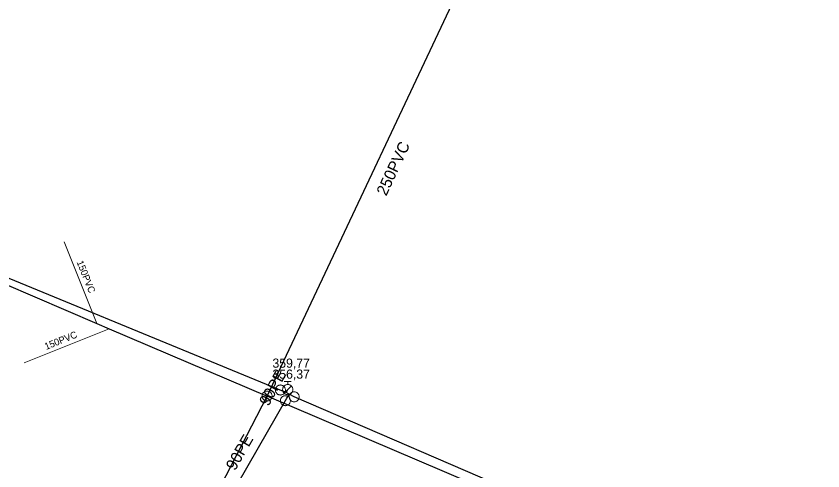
# Model space of a CAD drawing. Extents: x -741806 to -738704, y -1059275 to -1055387.
# Drawn here: x -740647.7 to -740577.2, y -1058173.6 to -1058133.8 of the extents above; entities that cross this region are included whole.
import ezdxf

# ---------------------------------------------------------------- set-up
doc = ezdxf.new("R2010")
doc.units = 0
doc.header["$LTSCALE"] = 0.4
for name, color, linetype, lineweight in [('2', 7, 'Continuous', 25), ('3', 7, 'Continuous', 13), ('50', 7, 'Continuous', 13), ('51', 7, 'Continuous', 13), ('52', 7, 'Continuous', 25), ('56', 7, 'Continuous', 13), ('6', 7, 'Continuous', 13)]:
    doc.layers.add(name, color=color, linetype=linetype, lineweight=lineweight)
for name, color, linetype in [('5', 7, 'Continuous'), ('53', 7, 'Continuous'), ('55', 7, 'Continuous')]:
    doc.layers.add(name, color=color, linetype=linetype)

msp = doc.modelspace()

# ---------------------------------------------------------------- linework, layer by layer
at = {"layer": '2'}
for points in [[(-740583.26, -1058185.25), (-740598.636, -1058178.666), (-740610.313, -1058173.665), (-740625.809, -1058167.03), (-740606.009, -1058125.064), (-740592.5, -1058086.389)], [(-740673.62, -1058146.55), (-740665.98, -1058149.83), (-740659.67, -1058152.54), (-740640.68, -1058160.7), (-740639.6, -1058161.169), (-740625.809, -1058167.03)], [(-740593.73, -1058213.72), (-740614.653, -1058204.646), (-740623.623, -1058200.756), (-740639.64, -1058193.81), (-740625.809, -1058167.03)]]:
    msp.add_lwpolyline(points, dxfattribs=at)
at = {"layer": '3'}
msp.add_lwpolyline([(-740626.211, -1058166.857), (-740626.226, -1058166.899), (-740626.237, -1058166.943), (-740626.244, -1058166.989), (-740626.246, -1058167.034), (-740626.243, -1058167.08), (-740626.235, -1058167.126), (-740626.222, -1058167.17), (-740626.206, -1058167.212), (-740626.184, -1058167.252), (-740626.158, -1058167.29), (-740626.129, -1058167.326), (-740626.096, -1058167.358), (-740626.06, -1058167.386), (-740626.022, -1058167.411), (-740625.98, -1058167.431), (-740625.937, -1058167.447), (-740625.893, -1058167.457), (-740625.848, -1058167.465), (-740625.802, -1058167.466), (-740625.756, -1058167.463), (-740625.711, -1058167.455), (-740625.668, -1058167.443), (-740625.624, -1058167.425), (-740625.584, -1058167.405), (-740625.546, -1058167.379), (-740625.511, -1058167.349), (-740625.479, -1058167.317), (-740625.45, -1058167.28), (-740625.426, -1058167.242), (-740625.406, -1058167.2), (-740625.39, -1058167.158), (-740625.379, -1058167.114), (-740625.372, -1058167.068), (-740625.371, -1058167.022), (-740625.374, -1058166.977), (-740625.381, -1058166.931), (-740625.394, -1058166.888), (-740625.412, -1058166.844), (-740625.433, -1058166.805), (-740625.458, -1058166.767), (-740625.487, -1058166.731), (-740625.52, -1058166.699), (-740625.556, -1058166.67), (-740625.594, -1058166.646), (-740625.636, -1058166.626), (-740625.679, -1058166.61), (-740625.723, -1058166.599), (-740625.768, -1058166.593), (-740625.814, -1058166.591), (-740625.86, -1058166.594), (-740625.905, -1058166.602), (-740625.949, -1058166.614), (-740625.992, -1058166.632), (-740626.032, -1058166.653), (-740626.071, -1058166.679), (-740626.106, -1058166.708), (-740626.137, -1058166.74), (-740626.166, -1058166.777), (-740626.19, -1058166.816), (-740626.211, -1058166.856)], dxfattribs=at)
at = {"layer": '50'}
for p, q in [((-740624.308, -1058165.766), (-740624, -1058165.766)), ((-740624, -1058166.017), (-740624, -1058165.766)), ((-740623.693, -1058165.766), (-740624, -1058165.766)), ((-740624, -1058166.464), (-740623.684, -1058166.152)), ((-740624, -1058166.464), (-740624.317, -1058166.781))]:
    msp.add_line(p, q, dxfattribs=at)
msp.add_lwpolyline([(-740623.556, -1058166.468), (-740623.558, -1058166.419), (-740623.563, -1058166.373), (-740623.576, -1058166.327), (-740623.593, -1058166.284), (-740623.612, -1058166.244), (-740623.639, -1058166.203), (-740623.668, -1058166.168), (-740623.701, -1058166.133), (-740623.736, -1058166.103), (-740623.776, -1058166.079), (-740623.817, -1058166.057), (-740623.86, -1058166.038), (-740623.906, -1058166.028), (-740623.952, -1058166.02), (-740623.998, -1058166.017), (-740624.044, -1058166.02), (-740624.089, -1058166.025), (-740624.135, -1058166.038), (-740624.179, -1058166.055), (-740624.222, -1058166.076), (-740624.26, -1058166.101), (-740624.297, -1058166.13), (-740624.33, -1058166.163), (-740624.359, -1058166.198), (-740624.386, -1058166.238), (-740624.408, -1058166.279), (-740624.424, -1058166.322), (-740624.438, -1058166.368), (-740624.443, -1058166.414), (-740624.45, -1058166.46), (-740624.447, -1058166.508), (-740624.439, -1058166.554), (-740624.428, -1058166.597), (-740624.412, -1058166.643), (-740624.39, -1058166.684), (-740624.366, -1058166.724), (-740624.336, -1058166.759), (-740624.304, -1058166.794), (-740624.266, -1058166.824), (-740624.228, -1058166.848), (-740624.185, -1058166.87), (-740624.142, -1058166.886), (-740624.099, -1058166.9), (-740624.05, -1058166.908), (-740624.004, -1058166.911), (-740623.958, -1058166.908), (-740623.912, -1058166.9), (-740623.866, -1058166.889), (-740623.823, -1058166.873), (-740623.78, -1058166.851), (-740623.742, -1058166.827), (-740623.704, -1058166.797), (-740623.672, -1058166.765), (-740623.642, -1058166.73), (-740623.618, -1058166.689), (-740623.594, -1058166.649), (-740623.577, -1058166.605), (-740623.567, -1058166.56), (-740623.559, -1058166.514)], close=True, dxfattribs=at)
at = {"layer": '51'}
for points in [[(-740624.206, -1058166.503), (-740624.208, -1058166.458), (-740624.215, -1058166.413), (-740624.227, -1058166.368), (-740624.243, -1058166.326), (-740624.264, -1058166.285), (-740624.289, -1058166.246), (-740624.318, -1058166.211), (-740624.35, -1058166.178), (-740624.386, -1058166.15), (-740624.424, -1058166.125), (-740624.465, -1058166.104), (-740624.508, -1058166.087), (-740624.552, -1058166.075), (-740624.597, -1058166.068), (-740624.643, -1058166.066), (-740624.689, -1058166.068), (-740624.734, -1058166.075), (-740624.778, -1058166.087), (-740624.821, -1058166.104), (-740624.862, -1058166.125), (-740624.9, -1058166.15), (-740624.936, -1058166.178), (-740624.968, -1058166.211), (-740624.997, -1058166.246), (-740625.022, -1058166.285), (-740625.043, -1058166.326), (-740625.059, -1058166.368), (-740625.071, -1058166.413), (-740625.078, -1058166.458), (-740625.081, -1058166.504), (-740625.078, -1058166.549), (-740625.071, -1058166.594), (-740625.059, -1058166.639), (-740625.043, -1058166.681), (-740625.022, -1058166.722), (-740624.997, -1058166.761), (-740624.968, -1058166.796), (-740624.936, -1058166.829), (-740624.9, -1058166.857), (-740624.862, -1058166.882), (-740624.821, -1058166.903), (-740624.778, -1058166.92), (-740624.734, -1058166.931), (-740624.689, -1058166.939), (-740624.643, -1058166.941), (-740624.597, -1058166.939), (-740624.552, -1058166.931), (-740624.508, -1058166.92), (-740624.465, -1058166.903), (-740624.424, -1058166.882), (-740624.386, -1058166.857), (-740624.35, -1058166.829), (-740624.318, -1058166.796), (-740624.289, -1058166.761), (-740624.264, -1058166.722), (-740624.243, -1058166.681), (-740624.227, -1058166.639), (-740624.215, -1058166.594), (-740624.208, -1058166.549), (-740624.206, -1058166.504)], [(-740623.771, -1058167.436), (-740623.772, -1058167.391), (-740623.78, -1058167.346), (-740623.792, -1058167.301), (-740623.808, -1058167.259), (-740623.829, -1058167.218), (-740623.853, -1058167.179), (-740623.883, -1058167.144), (-740623.915, -1058167.111), (-740623.951, -1058167.083), (-740623.989, -1058167.058), (-740624.03, -1058167.037), (-740624.073, -1058167.02), (-740624.117, -1058167.008), (-740624.162, -1058167.001), (-740624.208, -1058166.999), (-740624.254, -1058167.001), (-740624.299, -1058167.008), (-740624.343, -1058167.02), (-740624.386, -1058167.037), (-740624.427, -1058167.058), (-740624.465, -1058167.083), (-740624.5, -1058167.111), (-740624.532, -1058167.144), (-740624.562, -1058167.179), (-740624.587, -1058167.218), (-740624.608, -1058167.259), (-740624.624, -1058167.301), (-740624.636, -1058167.346), (-740624.643, -1058167.391), (-740624.646, -1058167.437), (-740624.643, -1058167.482), (-740624.636, -1058167.527), (-740624.624, -1058167.572), (-740624.608, -1058167.614), (-740624.587, -1058167.655), (-740624.562, -1058167.694), (-740624.532, -1058167.729), (-740624.5, -1058167.762), (-740624.465, -1058167.79), (-740624.427, -1058167.815), (-740624.386, -1058167.836), (-740624.343, -1058167.853), (-740624.299, -1058167.864), (-740624.254, -1058167.872), (-740624.208, -1058167.874), (-740624.162, -1058167.872), (-740624.117, -1058167.864), (-740624.073, -1058167.853), (-740624.03, -1058167.836), (-740623.989, -1058167.815), (-740623.951, -1058167.79), (-740623.915, -1058167.762), (-740623.883, -1058167.729), (-740623.853, -1058167.694), (-740623.829, -1058167.655), (-740623.808, -1058167.614), (-740623.792, -1058167.572), (-740623.78, -1058167.527), (-740623.772, -1058167.482), (-740623.771, -1058167.437)], [(-740623.002, -1058167.1), (-740623.004, -1058167.055), (-740623.012, -1058167.01), (-740623.024, -1058166.965), (-740623.039, -1058166.923), (-740623.061, -1058166.882), (-740623.085, -1058166.843), (-740623.115, -1058166.808), (-740623.147, -1058166.775), (-740623.183, -1058166.747), (-740623.22, -1058166.722), (-740623.262, -1058166.701), (-740623.304, -1058166.684), (-740623.348, -1058166.672), (-740623.394, -1058166.665), (-740623.44, -1058166.663), (-740623.485, -1058166.665), (-740623.531, -1058166.672), (-740623.575, -1058166.684), (-740623.617, -1058166.701), (-740623.659, -1058166.722), (-740623.696, -1058166.747), (-740623.732, -1058166.775), (-740623.764, -1058166.808), (-740623.794, -1058166.843), (-740623.818, -1058166.882), (-740623.84, -1058166.923), (-740623.855, -1058166.965), (-740623.867, -1058167.01), (-740623.875, -1058167.055), (-740623.877, -1058167.101), (-740623.875, -1058167.146), (-740623.867, -1058167.191), (-740623.855, -1058167.236), (-740623.84, -1058167.278), (-740623.818, -1058167.319), (-740623.794, -1058167.358), (-740623.764, -1058167.393), (-740623.732, -1058167.426), (-740623.696, -1058167.454), (-740623.659, -1058167.479), (-740623.617, -1058167.5), (-740623.575, -1058167.517), (-740623.531, -1058167.528), (-740623.485, -1058167.536), (-740623.44, -1058167.538), (-740623.394, -1058167.536), (-740623.348, -1058167.528), (-740623.304, -1058167.517), (-740623.262, -1058167.5), (-740623.22, -1058167.479), (-740623.183, -1058167.454), (-740623.147, -1058167.426), (-740623.115, -1058167.393), (-740623.085, -1058167.358), (-740623.061, -1058167.319), (-740623.039, -1058167.278), (-740623.024, -1058167.236), (-740623.012, -1058167.191), (-740623.004, -1058167.146), (-740623.002, -1058167.101)]]:
    msp.add_lwpolyline(points, dxfattribs=at)
at = {"layer": '52'}
msp.add_line((-740624.149, -1058166.73), (-740624, -1058166.46), dxfattribs=at)
for points in [[(-740623.879, -1058166.87), (-740624.149, -1058166.73), (-740624.359, -1058166.62), (-740655.649, -1058153.77), (-740657.079, -1058153.129), (-740662.969, -1058150.53), (-740675.52, -1058145), (-740679.778, -1058143.124), (-740679.969, -1058143.04)], [(-740640.916, -1058194.717), (-740640.617, -1058194.136), (-740635.78, -1058184.78), (-740630.059, -1058177.62), (-740624.085, -1058167.223), (-740623.879, -1058166.87)], [(-740375.044, -1058278.037), (-740378.824, -1058273.34), (-740394.89, -1058265.49), (-740400.5, -1058262.541), (-740409.548, -1058258.602), (-740416.798, -1058255.547), (-740435.443, -1058248.414), (-740442.241, -1058245.764), (-740464.396, -1058237.183), (-740473.081, -1058233.814), (-740479.142, -1058231.466), (-740486.337, -1058228.676), (-740513.46, -1058216.94), (-740523.39, -1058212.448), (-740529.642, -1058209.397), (-740536.912, -1058206.021), (-740544.259, -1058202.333), (-740565.754, -1058192.476), (-740572.673, -1058189.165), (-740573.656, -1058188.705), (-740595.099, -1058179.439), (-740602.27, -1058176.253), (-740623.44, -1058167.1), (-740623.879, -1058166.87)]]:
    msp.add_lwpolyline(points, dxfattribs=at)
at = {"layer": '56'}
for p, q in [((-740643.53, -1058153.55), (-740640.68, -1058160.7)), ((-740647.03, -1058164.129), (-740639.6, -1058161.169))]:
    msp.add_line(p, q, dxfattribs=at)

# ---------------------------------------------------------------- texts
at = {"layer": '5'}
msp.add_text('250PVC', height=1, rotation=65, dxfattribs=at).set_placement((-740615.393, -1058149.606))
at = {"layer": '53'}
for rotation, p in [(61, (-740625.688, -1058167.986)), (60, (-740628.606, -1058173.61))]:
    msp.add_text('90PE', height=1, rotation=rotation, dxfattribs=at).set_placement(p)
at = {"layer": '55'}
for rotation, p in [(292, (-740642.464, -1058155.33)), (22, (-740645.109, -1058163.008))]:
    msp.add_text('150PVC', height=0.6, rotation=rotation, dxfattribs=at).set_placement(p)
at = {"layer": '6'}
for s, p in [('359,77', (-740625.337, -1058164.556)), ('356,37', (-740625.337, -1058165.516))]:
    msp.add_text(s, height=0.8, dxfattribs=at).set_placement(p)

doc.saveas('drawing.dxf')
